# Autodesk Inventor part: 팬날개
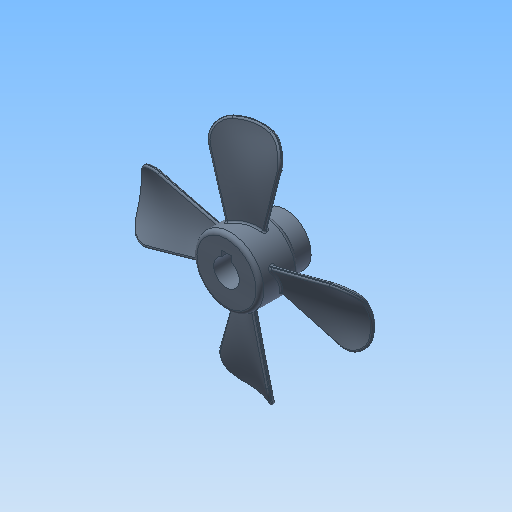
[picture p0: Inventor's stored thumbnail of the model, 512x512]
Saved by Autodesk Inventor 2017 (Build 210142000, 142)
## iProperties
Company: 한국ATC센터
Created: 2016-06
Part Number: 팬날개
Document SubType Name: Modeling
Designer: mdu
Density: 1.06 g/cm^3
Material: ABS 플라스틱
Mass: 29.2531 g
Surface Area: 148.135 cm^2
Volume: 27.5972 cm^3
Appearance: 강청색
Author: mdu
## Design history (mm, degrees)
sketch "스케치1"
  geometry: L1 (-15, 0)-(15, 0); L2 (-15, 0)-(-15, 17); L3 (-15, 17)-(5, 17); L4 (5, 17)-(5, 13); L5 (5, 13)-(15, 13); L6 (15, 13)-(15, 0); 2 further points
  constraints: 12 end point, 3 parallel, 2 perpendicular, 1 coincident, 1 horizontal, 1 midpoint
  dimensions: "d0" = 30 distance of L1.start L1.end; "d8" = 34 diameter of L3 L1; "d10" = 26 diameter of L5 L1; "d32" = 20 distance of L2.end L3.end
revolve "회전1" sketch "스케치1" stored, may be unused: angle "d11" = 90 deg
node "작업 평면2"
sketch "스케치7"
  geometry: L1 (-15, 17)-(5, 17) reference; L2 (-15, -17)-(5, -17) reference; L3 (-5, 17)-(-5, -17); A1 r 35 centre (-36.399, -13.457) between (-2, -7) and (-8, 7); 1 further point
  constraints: 2 end point, 2 midpoint, 2 point on circle, 1 centre point
  dimensions: "d36" = 35 radius of A1; "d37" = 10 distance from line of A1.start L2; "d38" = 10 distance from line of A1.end L1; "d45" = 3 distance from line of A1.end L3; "d46" = 3 distance from line of A1.start L3
sketch "3D 스케치1"
  geometry: L1 through (0, 0) direction (1, 0) reference; L2 through (0, 0) direction (1, 0) reference; 13 other entities
  constraints: 2 collinear
  node "투영 원본 위치 스케치7"
sketch "스케치8"
  geometry: L1 (-15, 17)-(5, 17) reference; L2 (-15, -17)-(5, -17) reference; L3 (-5, 17)-(-5, -17); A1 r 30 centre (-28.74, -3.591) between (-3, -19) and (-9, 19); 1 further point
  constraints: 2 end point, 2 midpoint, 2 point on circle, 1 centre point
  dimensions: "d43" = 30 radius of A1; "d47" = 4 distance from line of A1.end L3; "d48" = 2 distance from line of A1.start L3; "d58" = 2 distance from line of A1.end L1; "d59" = 2 distance from line of A1.start L2
sketch "3D 스케치2"
sketch "3D 스케치3"
feature "경계 패치1" sketch "3D 스케치2", "3D 스케치3" dims "d50" = 0
feature "연장1" dims "d55" = 2
feature "두껍게 하기1" dims "d51" = 2, "d52" = 2
sketch "스케치9"
  geometry: C1 r 59 at (0, 0); 1 further point
  constraints: 1 centre point, 1 coincident
  dimensions: "d60" = 118 diameter of C1
extrude "돌출2" sketch "스케치9" distance "d62" = 200; taper "d63" = 0 deg
fillet "모깎기6" dims "d64" = 10
fillet "모깎기7" dims "d66" = 0.8
fillet "모깎기8" dims "d67" = 0.8
sketch "스케치2"
  geometry: L1 (-2.5, 6)-(-2.5, 8.8); L2 (-2.5, 8.8)-(2.5, 8.8); L3 (2.5, 8.8)-(2.5, 6); A1 r 6.5 centre (0, 0) between (-2.5, 6) and (2.5, 6); 1 further point
  constraints: 6 end point, 2 parallel, 2 point on circle, 1 centre point, 1 coincident, 1 horizontal, 1 vertical
  dimensions: "d12" = 13 diameter of A1; "d13" = 5 distance of L1.end L2.end; "d14" = 15.3 dimension on A1 L2 (computed from d12)
extrude "돌출1" cut sketch "스케치2" stored distance "d15" = 10; taper "d16" = 0 deg
chamfer "모따기1" distance "d17" = 1; stored, may be unused: second distance "d18" = 2, angle "d19" = 45 deg
node "작업 평면1"
sketch "스케치3"
  geometry: L1 (5, -13)-(5, 13) reference; 3 further points
  constraints: 1 horizontal alignment, 1 midpoint
  dimensions: "d20" = 5 distance from line of L1 point (0, 0)
hole "구멍1" sketch "스케치3" at (0, 0) diameter "d21" = 2.459; stored, may be unused: countersink angle "d25" = 90 deg, drill point angle "d27" = 118 deg; dims "d22" = 6, "d23" = 4, "d24" = 2, "d26" = 8
fillet "모깎기9" dims "d77" = 2
fillet "모깎기10" dims "d78" = 2
fillet "모깎기11" dims "d79" = 2
node "솔리드1"
pattern_circular "원형 패턴1" dims angle "d69" = 360 deg
pattern_circular "원형 패턴2" dims angle "d72" = 360 deg
pattern_circular "원형 패턴3" dims angle "d75" = 360 deg
node "투영 원본 위치 스케치8"
node "곡면1"
node "곡면2"
node "곡면3"
node "곡면4"
feature "경계 패치2"
feature "경계 패치3"
feature "경계 패치4"
